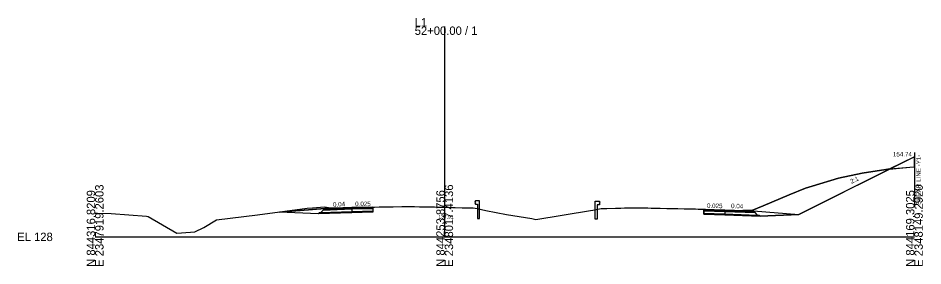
# Model space of a CAD drawing. Extents: x -26 to 2348258, y -10 to 844496.
# Drawn here: x 1308.9 to 1610.7, y 2990.3 to 3073 of the extents above; entities that cross this region are included whole.
import ezdxf

# ---------------------------------------------------------------- set-up
doc = ezdxf.new("R2010")
doc.units = 0
for name, color, linetype in [('Exist Cross Section Cell', 7, 'Continuous'), ('Exist XS Center Line Elevation Label', 7, 'Continuous'), ('Exist XS Ground Line', 7, 'Continuous'), ('Prop CMT Guardrail Graphics', 7, 'Continuous'), ('Prop CMT Pvmt Course 1', 7, 'Continuous'), ('Prop CMT Pvmt Course 2', 7, 'Continuous'), ('Prop CMT Pvmt Course 3', 7, 'Continuous'), ('Prop CMT Pvmt Course 4', 7, 'Continuous'), ('Prop CMT Pvmt Surface', 7, 'Continuous'), ('Prop CMT Shld Paved Course 1', 7, 'Continuous'), ('Prop CMT Shld Paved Course 2', 7, 'Continuous'), ('Prop CMT Shld Paved Course 3', 7, 'Continuous'), ('Prop CMT Shld Paved Course 4', 7, 'Continuous'), ('Prop CMT Slope Grass', 7, 'Continuous'), ('Prop CMT Subgrade Earthwork', 7, 'Continuous'), ('Prop XS Earthwork Shape', 7, 'Continuous'), ('Prop XS SE Text', 7, 'Continuous'), ('Prop XS Shear Point Element', 7, 'Continuous'), ('Prop XS Shear Point Label', 7, 'Continuous')]:
    doc.layers.add(name, color=color, linetype=linetype)

msp = doc.modelspace()

# ---------------------------------------------------------------- linework, layer by layer
at = {"layer": 'Exist Cross Section Cell'}
for p, q in [((1451.19, 3000), (1451.19, 3070.22)), ((1334.59, 3000), (1451.19, 3000)), ((1451.19, 3000), (1607.86, 3000))]:
    msp.add_line(p, q, dxfattribs=at)
at = {"layer": 'Exist XS Ground Line'}
msp.add_lwpolyline([(1334.59, 3007.88), (1335.41, 3007.9), (1339.92, 3007.83), (1351.74, 3006.86), (1352.25, 3006.82), (1361.8, 3001.25), (1366.36, 3001.53), (1367.9, 3001.67), (1370.81, 3003.17), (1375.09, 3005.64), (1388.75, 3007.36), (1405.3, 3009.59), (1407.07, 3009.71), (1411.11, 3010.04), (1413.05, 3009.66), (1414.83, 3009.68), (1415.25, 3009.69), (1416.09, 3009.72), (1417.66, 3009.76), (1419.12, 3009.8), (1419.52, 3009.81), (1420.14, 3009.82), (1421.34, 3009.84), (1422.11, 3009.86), (1424.68, 3009.91), (1425.02, 3009.92), (1427.39, 3009.96), (1427.75, 3009.97), (1429.32, 3010), (1430.32, 3010.02), (1430.97, 3010.03), (1433.96, 3010.06), (1436.91, 3010.09), (1437.55, 3010.1), (1438.58, 3010.11), (1439.62, 3010.1), (1440.12, 3010.1), (1441.16, 3010.09), (1442.81, 3010.07), (1443.16, 3010.07), (1444.78, 3010.04), (1445.81, 3010.03), (1446.59, 3010.01), (1447.8, 3009.99), (1448.82, 3009.97), (1450.72, 3009.92), (1451.24, 3009.91), (1451.78, 3009.88), (1452.47, 3009.86), (1453.82, 3009.84), (1454.67, 3009.81), (1457.03, 3009.74), (1457.63, 3009.72), (1459.22, 3009.67), (1460.68, 3009.64), (1461.38, 3009.56), (1462.05, 3009.42), (1464.86, 3008.8), (1471.78, 3007.46), (1480.23, 3006.13), (1481.54, 3005.81), (1499.82, 3008.76), (1500.62, 3008.91), (1503.42, 3009.45), (1504.58, 3009.49), (1505.28, 3009.52), (1508.18, 3009.59), (1509.96, 3009.63), (1511.18, 3009.66), (1512.3, 3009.67), (1513.43, 3009.69), (1514.11, 3009.69), (1515.37, 3009.68), (1517.27, 3009.66), (1518.98, 3009.64), (1520.07, 3009.61), (1521.96, 3009.57), (1523.01, 3009.55), (1525.3, 3009.5), (1525.75, 3009.48), (1526.54, 3009.48), (1528.95, 3009.44), (1531.11, 3009.4), (1531.58, 3009.4), (1531.89, 3009.39), (1533.29, 3009.36), (1534.85, 3009.32), (1535.71, 3009.3), (1537.59, 3009.26), (1538.13, 3009.22), (1540.46, 3009.12), (1540.81, 3009.1), (1541.43, 3009.07), (1543.79, 3008.96), (1544.24, 3008.93), (1545.24, 3008.85), (1545.94, 3008.88), (1551.9, 3008.83), (1553.66, 3008.77), (1557.47, 3010.38), (1566.04, 3014.03), (1571.54, 3016.3), (1573.81, 3016.94), (1582.5, 3019.59), (1590.45, 3021.3), (1598.35, 3022.53), (1606.29, 3023.31), (1607.86, 3023.41)], dxfattribs=at)
at = {"layer": 'Prop CMT Guardrail Graphics'}
for p, q in [((1461.46, 3012.08), (1461.19, 3011.79)), ((1462.79, 3012.08), (1461.46, 3012.08)), ((1462.79, 3006.08), (1462.79, 3012.08)), ((1461.19, 3011.79), (1461.46, 3011.5)), ((1461.46, 3011.5), (1461.19, 3011.21)), ((1461.19, 3011.21), (1461.46, 3010.91)), ((1461.46, 3010.91), (1462.13, 3010.91)), ((1462.13, 3010.91), (1462.13, 3006.08)), ((1501.43, 3005.88), (1501.43, 3011.88)), ((1501.43, 3011.88), (1502.76, 3011.88)), ((1502.76, 3010.71), (1502.09, 3010.71)), ((1502.09, 3010.71), (1502.09, 3005.88)), ((1502.76, 3011.88), (1503.03, 3011.59)), ((1503.03, 3011.59), (1502.76, 3011.3)), ((1502.76, 3011.3), (1503.03, 3011)), ((1503.03, 3011), (1502.76, 3010.71)), ((1462.13, 3006.08), (1462.79, 3006.08)), ((1502.09, 3005.88), (1501.43, 3005.88))]:
    msp.add_line(p, q, dxfattribs=at)
at = {"layer": 'Prop CMT Pvmt Course 1'}
for p, q in [((1420.19, 3009.66), (1420.19, 3009.78)), ((1420.19, 3009.53), (1420.19, 3009.78)), ((1544.59, 3008.96), (1544.59, 3009.08)), ((1544.59, 3008.83), (1544.59, 3009.08))]:
    msp.add_line(p, q, dxfattribs=at)
at = {"layer": 'Prop CMT Pvmt Course 2'}
for p, q in [((1420.19, 3009.53), (1410.93, 3009.16)), ((1427.19, 3009.71), (1420.19, 3009.53)), ((1420.19, 3009.2), (1420.19, 3009.53)), ((1537.59, 3009.01), (1544.59, 3008.83)), ((1544.59, 3008.83), (1554.41, 3008.44)), ((1544.59, 3008.5), (1544.59, 3008.83))]:
    msp.add_line(p, q, dxfattribs=at)
at = {"layer": 'Prop CMT Pvmt Course 3'}
for p, q in [((1420.19, 3009.2), (1410.58, 3008.81)), ((1427.19, 3009.37), (1420.19, 3009.2)), ((1420.19, 3009.2), (1420.19, 3008.4)), ((1427.19, 3009.37), (1427.19, 3008.58)), ((1537.59, 3008.67), (1544.59, 3008.5)), ((1537.59, 3008.67), (1537.59, 3007.88)), ((1544.59, 3008.5), (1554.76, 3008.09)), ((1544.59, 3008.5), (1544.59, 3007.7))]:
    msp.add_line(p, q, dxfattribs=at)
at = {"layer": 'Prop CMT Pvmt Course 4'}
for p, q in [((1420.19, 3008.07), (1408.94, 3007.65)), ((1420.19, 3008.41), (1409.78, 3008.01)), ((1427.19, 3008.58), (1420.19, 3008.41)), ((1420.19, 3008.07), (1420.19, 3008.4)), ((1427.19, 3008.25), (1420.19, 3008.07)), ((1427.19, 3008.25), (1427.19, 3008.58)), ((1537.59, 3007.88), (1544.59, 3007.71)), ((1537.59, 3007.55), (1537.59, 3007.88)), ((1537.59, 3007.55), (1544.59, 3007.37)), ((1544.59, 3007.71), (1555.56, 3007.29)), ((1544.59, 3007.37), (1544.59, 3007.7)), ((1544.59, 3007.37), (1556.4, 3006.93))]:
    msp.add_line(p, q, dxfattribs=at)
at = {"layer": 'Prop CMT Pvmt Surface'}
for p, q in [((1420.19, 3009.78), (1411.19, 3009.42)), ((1427.19, 3009.96), (1420.19, 3009.78)), ((1537.59, 3009.26), (1544.59, 3009.08)), ((1544.59, 3009.08), (1554.15, 3008.7))]:
    msp.add_line(p, q, dxfattribs=at)
at = {"layer": 'Prop CMT Shld Paved Course 1'}
for p, q in [((1411.19, 3009.42), (1410.93, 3009.17)), ((1554.15, 3008.7), (1554.41, 3008.44))]:
    msp.add_line(p, q, dxfattribs=at)
at = {"layer": 'Prop CMT Shld Paved Course 2'}
for p, q in [((1410.93, 3009.17), (1410.59, 3008.82)), ((1554.41, 3008.44), (1554.75, 3008.1))]:
    msp.add_line(p, q, dxfattribs=at)
at = {"layer": 'Prop CMT Shld Paved Course 3'}
for p, q in [((1409.78, 3008.01), (1410.59, 3008.82)), ((1555.56, 3007.29), (1554.75, 3008.1))]:
    msp.add_line(p, q, dxfattribs=at)
at = {"layer": 'Prop CMT Shld Paved Course 4'}
for p, q in [((1409.28, 3007.99), (1408.95, 3007.66)), ((1409.78, 3008.01), (1409.28, 3007.99)), ((1555.56, 3007.29), (1556.06, 3007.27)), ((1556.06, 3007.27), (1556.39, 3006.94))]:
    msp.add_line(p, q, dxfattribs=at)
at = {"layer": 'Prop CMT Slope Grass'}
for p, q in [((1607.86, 3026.74), (1569.36, 3007.48)), ((1607.86, 3026.74), (1607.86, 3023.41)), ((1411.19, 3009.42), (1396.1, 3008.21)), ((1554.15, 3008.7), (1569.36, 3007.48))]:
    msp.add_line(p, q, dxfattribs=at)
at = {"layer": 'Prop CMT Subgrade Earthwork'}
for p, q in [((1427.19, 3009.96), (1427.19, 3008.25)), ((1427.19, 3009.96), (1427.19, 3008.25)), ((1537.59, 3009.26), (1537.59, 3007.55)), ((1537.59, 3009.26), (1537.59, 3007.55)), ((1408.94, 3007.65), (1396.1, 3008.21)), ((1420.19, 3008.07), (1408.94, 3007.65)), ((1544.59, 3007.37), (1556.4, 3006.93)), ((1556.4, 3006.93), (1569.36, 3007.48))]:
    msp.add_line(p, q, dxfattribs=at)
for points in [[(1427.19, 3008.25), (1420.19, 3008.07)], [(1537.59, 3007.55), (1544.59, 3007.37)]]:
    msp.add_lwpolyline(points, dxfattribs=at)
at = {"layer": 'Prop XS Earthwork Shape'}
for points in [[(1606.29, 3023.31), (1607.86, 3023.41), (1607.86, 3026.74), (1599.72, 3022.66)], [(1554.15, 3008.7), (1569.36, 3007.48), (1599.72, 3022.66), (1598.35, 3022.53), (1590.45, 3021.3), (1582.5, 3019.59), (1573.81, 3016.94), (1571.54, 3016.3), (1566.04, 3014.03), (1557.47, 3010.38), (1553.66, 3008.77), (1551.9, 3008.83), (1550.66, 3008.84)], [(1427.19, 3009.96), (1427.19, 3008.25), (1420.19, 3008.07), (1408.94, 3007.65), (1396.1, 3008.21), (1411.19, 3009.42), (1420.19, 3009.78)], [(1427.19, 3009.96), (1427.19, 3008.25), (1420.19, 3008.07), (1408.94, 3007.65), (1396.1, 3008.21), (1411.19, 3009.42), (1420.19, 3009.78)], [(1554.15, 3008.7), (1569.36, 3007.48), (1556.4, 3006.93), (1544.59, 3007.37), (1537.59, 3007.55), (1537.59, 3009.26), (1538.13, 3009.22), (1540.46, 3009.12), (1540.81, 3009.1), (1541.43, 3009.07), (1543.79, 3008.96), (1544.24, 3008.93), (1545.24, 3008.85), (1545.94, 3008.88), (1550.66, 3008.84)]]:
    msp.add_lwpolyline(points, close=True, dxfattribs=at)
at = {"layer": 'Prop XS Shear Point Element'}
msp.add_line((1607.86, 3028.19), (1607.86, 3010.06), dxfattribs=at)

# ---------------------------------------------------------------- texts
at = {"layer": 'Exist Cross Section Cell'}
for s, p in [('L1', (1441.19, 3070.22)), ('52+00.00 / 1', (1441.19, 3067.42)), ('EL 128', (1308.59, 2998.6))]:
    msp.add_text(s, height=2.8, dxfattribs=at).set_placement(p)
for s, p in [('N 844316.8209', (1334.59, 2990)), ('E 2347919.2603', (1337.39, 2990)), ('N 844253.8756', (1451.19, 2990)), ('E 2348017.4136', (1453.99, 2990)), ('N 844169.3025', (1607.86, 2990)), ('E 2348149.2920', (1610.66, 2990))]:
    msp.add_text(s, height=2.8, rotation=90, dxfattribs=at).set_placement(p)
at = {"layer": 'Exist XS Center Line Elevation Label'}
msp.add_text('137.91', height=1.2, dxfattribs=at).set_placement((1449.08, 3006.12))
at = {"layer": 'Prop XS SE Text'}
for s, rotation, p in [('2:1', 26.5651, (1586.88, 3017.7)), ('0.04', 2.2471, (1413.97, 3010.06)), ('0.025', 358.5679, (1538.66, 3009.69)), ('0.04', 358.0849, (1546.69, 3009.6))]:
    msp.add_text(s, height=1.5, rotation=rotation, dxfattribs=at).set_placement(p)
msp.add_text('0.025', height=1.5, dxfattribs=at).set_placement((1421.33, 3010.26))
at = {"layer": 'Prop XS Shear Point Label'}
msp.add_text('154.74', height=1.5, dxfattribs=at).set_placement((1600.7, 3026.83))
msp.add_text('SHEAR LINE -Y1-', height=1.5, rotation=90, dxfattribs=at).set_placement((1610, 3010.66))

doc.saveas('drawing.dxf')
